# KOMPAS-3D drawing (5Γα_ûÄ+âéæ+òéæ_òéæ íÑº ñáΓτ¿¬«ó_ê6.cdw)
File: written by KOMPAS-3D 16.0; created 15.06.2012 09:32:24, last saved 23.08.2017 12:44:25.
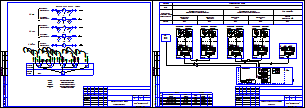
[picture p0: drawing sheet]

Sheets 1-2: A3, landscape

Title block, sheet 1: name: Руководство по эксплуатации; sheet number: 1; sheets: 27; organisation: ООО"Интелприбор"; sheet format: A3; stored path: W:\Users\smirnov_v\Desktop\шаблоны\4-х трубка\4-х трубка ГВС-max.cdw / D:\Проекты\Лыткарино\ул. Квартал 3А, д.25\710.74 РП.cdw; file name: 4-х трубка ГВС-max.cdw / 710.74 РП.cdw; cell 51: МО, Воскресенсикй р-н, п. Хорлово, ул. Интернациональная, д. 4; cell 320: Р
Title block, sheet 2: sheet number: 2

Views: Вид 2, Вид 3
Referenced files in C:\Program Files (x86)\ASCON\KOMPAS-3D V16\Sys\: spds.lcs, EngSys.lcs, GRAPHIC.LHS
Referenced files: graphic.tdp
Referenced files in W:\Users\smirnov_v\Desktop\шаблоны\4-х трубка\: 4-х трубка ГВС-max.cdw
Referenced files in D:\Проекты\Лыткарино\ул. Квартал 3А, д.25\: 710.74 РП.cdw
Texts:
  Смирнов В.С.
  УУ-3423
  GOST Common
  Normal
  List Paragraph
  heading 3
  для схемы
  txt
  Т0-элементы
  Плата подключений
  Агрегат
  Системный блок  МКТС
  Среда
  Вода
  параметра и место
  отбора импульса
  Учет тепловой энергии и
  теплоносителя системы отопления
  Подающий
  трубопровод
  отопления
  Обратный
  расхода горячей водысистемы ГВС
  Вводной
  трубопровод ХВС
  Узел учета ХВС
  ГВС
  ИМ1
  ИМ2
  ИМ3
  ИМ4
  ИМ5
  СБ МКТС
  ВРУ
  UP+
  UP-
  ИМП
  Лин
  Измерительный
  модуль М121
  Pt 100
  Преобразователь
  температуры
  давления
  каб.
  Начало
  трассы
  Трассы
  Марка
  Проложен
  Изм. модуль (Т1)
  Изм. модуль (Т2)
  Изм. модуль (Т3)
  Изм. модуль (Т4)
  Изм. модуль (В1)
  ВРУ 220В, 50 Гц
  ИМ (Т1)
  ИМ (Т3)
  FTP
  ПВС
  Конец
  Кол-во и
  сеч. жил
  Длина,
  приборы
  по месту
  шкаф
  учета
  UQIES
  Преобразователь расхода
  Термопреобразователь
  Преобразователь давления
  Преобразователь цифровой
  Системный блок МКТС
  Функциональная схема
  УУГВС
  УУТЭ
  УУХВС
  Размеры, параметризация
  сит. план
  подача ГВС
  обратка ГВС
  хвс
  обратка
  POLYLINE_STYLE_0.25_RGB_0_0_0
  стены
  Основная (не является границей для штриховки)
  POLYLINE_STYLE_0.18_RGB_0_0_0
  ХВС
  зеленая
  Красная тонкая
  арматура
  Подача
  Скрытая линия
  Ось Z
  Ось Y
  Ось X
  Образующая трубопровода (проектируемого)
  Трубопровод толщиной 0.6мм (одна линия)
  Трубопровод толщиной 1.2мм (одна линия)
  Трубопровод толщиной 1.0мм (одна линия)
  Трубопровод толщиной 0.8мм (одна линия)
  Трубопровод существующий (одна линия)
  Трубопровод невидимый (одна линия)
  Трубопровод демонтируемый (одна линия)
  Осевая трубопровода
  Осевая трубопровода (демонтируемого)
  Образующая трубопровода (существующего)
  Образующая трубопровода (невидимого)
  Изолированный трубопровод проектируемый (одна линия)
  Изолированный трубопровод существующий (одна линия)
  Образующая изоляции
  Изоляция
  Изолированный трубопровод невидимый (одна линия)
  Штрих пвс 075
  штрих пвс 2,5
  существующее оборудование
  Существующее оборудование
  K5LT_BASIC_RGB_0_0_255_THICK_0.53
  POLYLINE_STYLE_1.51_RGB_0_0_255
  POLYLINE_STYLE_0.50_RGB_128_128_128
  K5LT_AXLED_RGB_255_128_0_SC_1_THICK_0.18
  ACAD_ISO04W100_RGB_0_0_0_SC_1_THICK_0.18
  тонкая черная
  тонкая красная
  тонкая синяя
  тонкая оранж
  красн штрих
  пломбировка
  Провода
  синий штрих
  Стили документа
  G2co
  расход вторичной воды объемный
  расход вторичной воды объемный при 70гр
  Gco
  расход теплоносителя массовый
  расход теплоносит объемн подающ
  расход теплоносит объемн обр
  Лапир
  Ghvs
  Im1
  Im2
  Im3
  Im4
  Im5
  Khvs
  норматив ХВС
  число подъездов
  число этажей
  Nkv
  число квартир
  тепловая нагрузка на отопление
  сумма Q
  Qgvs
  тепловая нагрузка ГВС
  тепловая нагрузка на циркуляцию ГВС
  иммитовставка или под манометр
  ro1
  ro2
  ro3
  ro4
  верх предел темп граф
  нижн предел темп граф
  темп подачи ГВС
  темп обр ГВС
  темр хол воды
  vzdh
  Kchn
  Ktp
  Knp
  tnv
  Vклап
  KLP
  RPD
  RDS
  PUMP
  ro5
  beta
  tnv98
  Shifr
  Переход ГОСТ 17378-2001
  Переход
  ГОСТ
  Сталь 09Г2С ГОСТ 19281-89
  Втулка 20x50
  Лит-Масса-Масштаб
  Материал-Предприятие
  Title Specification
  Body Specification ( left align )
  Body Specificaton ( centered )
  Поз.
  Кол.
  Приме-
  чание
  Таблица спецификации
  Засыпка
  Штрих3
  Штрих2
  Штрих1
  Песок
  Штр0.5пр7
  Штр0.5пр12
  Штр0.3пр10
  Штр1.4пр21.21
  Штр1пр15
  Штр2.12пр35
  Штр1.5пр25
  Штр2.82пр42.42
  Штр2пр30
  SACNCR_ISO 1
  Электрощитовая
  Пр-1
  Ок-1
  Обозначение стандарта
  Типоразмер
  Пояснительная записка
  автоматизации
  Рабочие чертежи основного комплекта. ГОСТ Р 21.1101-2009 Ф3
  Стадия
  Лист
  Листов
  Изм.
  Кол.уч.
  №док.
  Подп.
  Дата
  Разраб.
  Пров.
  Т.контр.
  Н.контр.
  Утв.
  Изменение
  Номер документа
  Подпись
  Наименование объекта строительства, в состав которого входит здание, наим. микр
  Наименование здания (сооружения)
  Порядковый номер листа
  Количество листов в документе
  Наименование изображения
  Индекс предприятия, выпускающего документ
  Инв. № подл.
  Подп. и дата
  Взам. инв. №
  Инвентарный номер подлинника
  Подпись принявшего подлинник на хранение
  Инвентарный номер подлинника, взамен которого выпущен данный подлинник
  Согласовано
  Формат листа
  Согласование
  03 Рабочие чертежи основного комплекта. ГОСТ Р 21.1101-2009 Ф3
  Схема соединений внешних
  проводок
Dimensions and other numbers on the sheet: 1; 2; 3; 6; 5; 4; 220В; 50Гц; 4-20; 2x2x0,52; 3х0,75; 20; 11; 14; 15; 19; 10; 7; 16; 0; 5,0; 3,2388; 0,0400; 40; 95; 3,1876; 4,5; 0,0; 0,0000; 70; 9; 12; 13; 8; 17; 1,2,3,4,5; 6,7,8,9; 10,11,12,13; 14,15,16,17,18; 18; 09Г2С; 27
